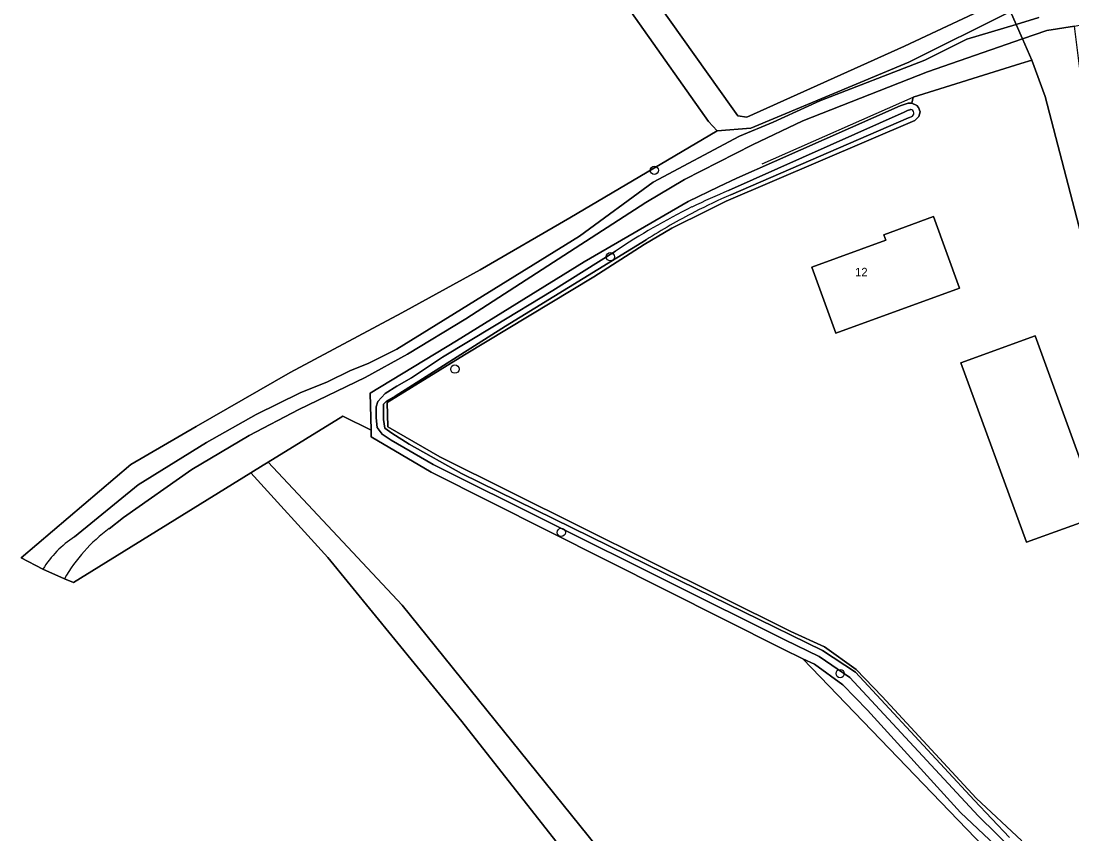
# Model space of a CAD drawing. Extents: x 163859 to 164644, y 379566 to 382155.
# Drawn here: x 164255.7 to 164380.2, y 381497.9 to 381594.2 of the extents above; entities that cross this region are included whole.
import ezdxf

# ---------------------------------------------------------------- set-up
doc = ezdxf.new("R2010")
doc.units = 0
for name, color, linetype in [('IMGEO_Boom', 7, 'Continuous'), ('IMGEO_Bouwland', 7, 'Continuous'), ('IMGEO_Erf', 7, 'Continuous'), ('IMGEO_Grasland_overig', 7, 'Continuous'), ('IMGEO_Groenvoorziening', 7, 'Continuous'), ('IMGEO_Hek', 7, 'Continuous'), ('IMGEO_Oever', 7, 'Continuous'), ('IMGEO_Pand', 7, 'Continuous'), ('IMGEO_Pand_nummerreeks', 7, 'Continuous'), ('IMGEO_Rijbaan_lokaal_onverhard', 7, 'Continuous'), ('IMGEO_Waterloop', 7, 'Continuous')]:
    doc.layers.add(name, color=color, linetype=linetype)

msp = doc.modelspace()

# ---------------------------------------------------------------- linework, layer by layer
at = {"layer": 'IMGEO_Boom'}
for centre in [(164330.75, 381576.5), (164325.53, 381566.25), (164307.12, 381552.94), (164319.72, 381533.59), (164352.76, 381516.86)]:
    msp.add_circle(centre, 0.489, dxfattribs=at)
at = {"layer": 'IMGEO_Bouwland'}
msp.add_lwpolyline([(164355.54, 381450.6), (164307.96, 381511.18), (164292.08, 381530.61), (164282.94, 381540.64), (164261.94, 381527.66), (164260.87, 381528.09), (164258.3, 381529.24), (164255.73, 381530.58), (164268.74, 381541.65), (164276.47, 381546.15), (164287.59, 381552.54), (164300.85, 381559.61), (164310.1, 381564.69), (164320.74, 381570.88), (164338.17, 381581.17), (164337.15, 381582.3), (164311.21, 381619.04)], dxfattribs=at)
msp.add_lwpolyline([(164285.02, 381541.92), (164300.88, 381524.96), (164324.9, 381495.18), (164345.91, 381468.69), (164361.95, 381448.81), (164380.14, 381426.39), (164393.19, 381411.03), (164409.6, 381438.92), (164409.07, 381444.14), (164407.24, 381453.04), (164404.26, 381474.32), (164397.81, 381497.74), (164374.92, 381491), (164348.35, 381518.62), (164345.94, 381519.8), (164304.33, 381540.74), (164297.21, 381544.93), (164297.2, 381545.69), (164293.83, 381547.35)], close=True, dxfattribs=at)
at = {"layer": 'IMGEO_Erf'}
for points in [[(164360.65, 381617.95), (164344.82, 381642.8), (164342.85, 381642.58), (164338.8, 381641.77), (164327.26, 381636.72), (164319.71, 381632.45), (164314.46, 381629.79), (164310.8, 381628.87), (164308.85, 381629.06), (164308.78, 381627.38), (164311.6, 381623.07), (164325.22, 381604.63), (164340.03, 381583.8), (164340.63, 381582.95), (164341.72, 381582.81), (164360.39, 381591.19), (164372.33, 381596.86), (164373.03, 381597.19), (164374.16, 381597.69), (164365.76, 381610.9)], [(164352.26, 381557.21), (164349.42, 381565.03), (164358.15, 381568.22), (164357.92, 381568.87), (164363.81, 381571.02), (164366.9, 381562.54)], [(164367.06, 381553.7), (164375.84, 381556.9), (164383.59, 381535.61), (164374.81, 381532.42)]]:
    msp.add_lwpolyline(points, close=True, dxfattribs=at)
msp.add_lwpolyline([(164394.23, 381519.23), (164377.05, 381585.25), (164375.48, 381589.55), (164374.16, 381589.15), (164361.39, 381585.17), (164361.25, 381584.45), (164361.82, 381584.19), (164362.04, 381583.93), (164362.24, 381583.41), (164362.09, 381582.86), (164361.61, 381582.39), (164339.27, 381572.83), (164337.03, 381571.73), (164332.8, 381569.66), (164329.55, 381567.7), (164323.57, 381563.86), (164308.27, 381554.65), (164299.1, 381548.97), (164299.19, 381546.09), (164305.32, 381542.54), (164346.92, 381521.84), (164350.89, 381520.01), (164354.66, 381517.34), (164357.74, 381514.15), (164368.85, 381502.09), (164374.28, 381497.03)], dxfattribs=at)
at = {"layer": 'IMGEO_Grasland_overig'}
for points in [[(164321.9, 381568.69), (164330.62, 381575.1), (164340.85, 381580.53), (164344.81, 381582.22), (164350.33, 381584.74), (164362.79, 381589.53), (164367.77, 381592.02), (164373.62, 381593.79), (164372.93, 381595.33), (164360.91, 381589.33), (164342.17, 381581.51), (164338.17, 381581.17), (164320.74, 381570.88), (164310.1, 381564.69), (164300.85, 381559.61), (164287.59, 381552.54), (164276.47, 381546.15), (164268.74, 381541.65), (164255.73, 381530.58), (164258.3, 381529.24)], [(164329.74, 381572.7), (164334.32, 381575.4), (164342.38, 381579.5), (164348.34, 381582.35), (164363.11, 381588.17), (164374.37, 381592.06), (164373.62, 381593.79), (164367.77, 381592.02), (164362.79, 381589.53), (164350.33, 381584.74), (164344.81, 381582.22), (164340.85, 381580.53), (164330.62, 381575.1), (164321.9, 381568.69), (164300.23, 381555.29), (164296.85, 381553.59), (164294.75, 381552.79), (164292.05, 381551.44), (164288.81, 381550.12), (164283.59, 381547.57), (164277.71, 381544.24), (164269.61, 381539.21), (164262.05, 381533.06)], [(164260.87, 381528.09), (164261.94, 381527.66), (164282.94, 381540.64), (164284.42, 381541.54), (164285.02, 381541.92), (164293.83, 381547.35), (164297.2, 381545.69), (164297.1, 381550.07), (164307.31, 381556.3), (164322.44, 381565.66), (164334.75, 381572.82), (164338.35, 381574.54), (164340.51, 381575.55), (164344.96, 381577.54), (164359.85, 381584.14), (164360.81, 381584.45), (164361.25, 381584.45), (164361.39, 381585.17), (164374.16, 381589.15), (164375.48, 381589.55), (164374.37, 381592.06), (164363.11, 381588.17), (164348.34, 381582.35), (164342.38, 381579.5), (164334.32, 381575.4), (164329.74, 381572.7), (164308.43, 381558.91), (164301.49, 381554.72), (164296.49, 381551.95), (164288.63, 381548.14), (164282.77, 381545.07), (164275.97, 381541.06), (164267.86, 381535.37), (164266.17, 381534.03)], [(164266.17, 381534.03), (164267.86, 381535.37), (164275.97, 381541.06), (164282.77, 381545.07), (164288.63, 381548.14), (164296.49, 381551.95), (164301.49, 381554.72), (164308.43, 381558.91), (164329.74, 381572.7)], [(164262.05, 381533.06), (164269.61, 381539.21), (164277.71, 381544.24), (164283.59, 381547.57), (164288.81, 381550.12), (164292.05, 381551.44), (164294.75, 381552.79), (164296.85, 381553.59), (164300.23, 381555.29), (164321.9, 381568.69)], [(164324.9, 381495.18), (164300.88, 381524.96), (164285.02, 381541.92), (164284.42, 381541.54), (164282.94, 381540.64), (164292.08, 381530.61), (164307.96, 381511.18), (164355.54, 381450.6)], [(164258.3, 381529.24), (164260.87, 381528.09)]]:
    msp.add_lwpolyline(points, dxfattribs=at)
for points in [[(164392.11, 381552.47), (164390.65, 381553.68), (164390.08, 381554.71), (164388.77, 381561.19), (164381.76, 381583.47), (164380.51, 381593.56), (164377.23, 381593.05), (164374.37, 381592.06), (164375.48, 381589.55), (164377.05, 381585.25), (164394.23, 381519.23), (164389.32, 381551.69)], [(164403.38, 381480.67), (164403.25, 381483.47), (164403.76, 381484.04), (164404.03, 381484.15), (164403.46, 381487.71), (164402.44, 381487.77), (164402.22, 381489.44), (164399.72, 381498.97), (164381.15, 381493.56), (164378.9, 381492.55), (164376.45, 381492.51), (164374.19, 381493.46), (164372.5, 381495.24), (164367, 381500.41), (164355.98, 381512.51), (164353.09, 381515.54), (164349.7, 381517.97), (164348.35, 381518.62), (164374.92, 381491), (164397.81, 381497.74), (164404.26, 381474.32)]]:
    msp.add_lwpolyline(points, close=True, dxfattribs=at)
for centre, radius, start, end in [((164277.4, 381518.7), 19.01, 126.2236, 150.3885), ((164277.4, 381518.7), 19.01, 126.2236, 150.3885), ((164269.14, 381522.37), 12.83, 123.5518, 147.6149), ((164269.14, 381522.37), 12.83, 123.5518, 147.6149)]:
    msp.add_arc(centre, radius, start, end, dxfattribs=at)
at = {"layer": 'IMGEO_Groenvoorziening'}
msp.add_lwpolyline([(164357.73, 381627.06), (164346.74, 381643.35), (164343.74, 381644.16), (164341.85, 381643.92), (164342.85, 381642.58), (164344.82, 381642.8), (164360.65, 381617.95), (164365.76, 381610.9), (164374.16, 381597.69), (164373.03, 381597.19), (164373.82, 381595.78), (164372.93, 381595.33), (164373.62, 381593.79), (164376.28, 381594.59)], dxfattribs=at)
at = {"layer": 'IMGEO_Hek'}
for points in [[(164374.16, 381589.15), (164375.48, 381589.55)], [(164343.52, 381577.27), (164361.39, 381585.17)]]:
    msp.add_lwpolyline(points, dxfattribs=at)
at = {"layer": 'IMGEO_Oever'}
for points in [[(164374.28, 381497.03), (164368.85, 381502.09), (164357.74, 381514.15), (164354.66, 381517.34), (164350.89, 381520.01), (164346.92, 381521.84), (164305.32, 381542.54), (164299.19, 381546.09), (164299.1, 381548.97), (164308.27, 381554.65), (164323.57, 381563.86), (164329.55, 381567.7), (164332.8, 381569.66), (164337.03, 381571.73), (164339.27, 381572.83), (164361.61, 381582.39), (164362.09, 381582.86), (164362.24, 381583.41), (164362.04, 381583.93), (164361.82, 381584.19), (164361.25, 381584.45), (164360.81, 381584.45), (164359.85, 381584.14), (164344.96, 381577.54), (164340.51, 381575.55), (164338.35, 381574.54), (164334.75, 381572.82), (164322.44, 381565.66), (164307.31, 381556.3), (164297.1, 381550.07), (164297.2, 381545.69), (164297.21, 381544.93), (164304.33, 381540.74), (164345.94, 381519.8), (164348.35, 381518.62), (164349.7, 381517.97), (164353.09, 381515.54), (164355.98, 381512.51), (164367, 381500.41), (164372.5, 381495.24)], [(164339.54, 381574.12), (164360.32, 381583.37), (164360.72, 381583.6), (164361.11, 381583.72)], [(164361.17, 381582.83), (164360.96, 381582.74), (164360.87, 381582.71), (164339.8, 381573.6)], [(164329.77, 381568.26), (164313.12, 381558.01), (164300.03, 381549.74), (164299, 381549.16), (164298.67, 381548.78), (164298.67, 381546.95), (164298.84, 381545.93), (164299.65, 381545.33), (164301.71, 381544.03), (164307.92, 381540.57), (164331.96, 381528.77), (164350.67, 381519.59), (164354.57, 381517.03), (164368.63, 381501.86), (164372.82, 381497.44)], [(164311.83, 381558.05), (164318.74, 381562.27), (164326.13, 381566.92)], [(164373.54, 381495.65), (164369.1, 381500), (164353.9, 381516.4), (164350.27, 381518.88), (164346.22, 381520.84), (164304.55, 381541.63), (164299.58, 381544.5), (164298.49, 381545.22), (164297.92, 381546.04), (164297.78, 381547.18), (164297.8, 381548.46), (164298, 381549.11), (164298.88, 381550.05), (164300.24, 381550.9), (164301.98, 381551.89), (164305.64, 381554.34), (164311.83, 381558.05)]]:
    msp.add_lwpolyline(points, dxfattribs=at)
for centre, radius, start, end in [((164361.02, 381583.27), 0.461, 289.4939, 79.0169), ((164369.92, 381501.27), 78.92, 112.6358, 116.099), ((164370.05, 381504.51), 75.42, 113.6483, 117.2335), ((164369.5, 381502.22), 77.89, 116.129, 123.8321), ((164369.14, 381506.27), 73.44, 117.2293, 122.4145)]:
    msp.add_arc(centre, radius, start, end, dxfattribs=at)
at = {"layer": 'IMGEO_Pand'}
for points in [[(164352.26, 381557.21), (164366.9, 381562.54), (164363.81, 381571.02), (164357.92, 381568.87), (164358.15, 381568.22), (164349.42, 381565.03)], [(164374.81, 381532.42), (164383.59, 381535.61), (164375.84, 381556.9), (164367.06, 381553.7)]]:
    msp.add_lwpolyline(points, close=True, dxfattribs=at)
at = {"layer": 'IMGEO_Rijbaan_lokaal_onverhard'}
msp.add_lwpolyline([(164376.28, 381594.59), (164373.62, 381593.79), (164374.37, 381592.06), (164377.23, 381593.05), (164380.51, 381593.56), (164384.86, 381594.48), (164414.14, 381600.68)], dxfattribs=at)
at = {"layer": 'IMGEO_Waterloop'}
for points in [[(164311.21, 381619.04), (164337.15, 381582.3), (164338.17, 381581.17), (164342.17, 381581.51), (164360.91, 381589.33), (164372.93, 381595.33)], [(164372.33, 381596.86), (164360.39, 381591.19), (164341.72, 381582.81), (164340.63, 381582.95), (164340.03, 381583.8), (164325.22, 381604.63)], [(164361.11, 381583.72), (164360.72, 381583.6), (164360.32, 381583.37), (164339.54, 381574.12)], [(164339.8, 381573.6), (164360.87, 381582.71), (164360.96, 381582.74), (164361.17, 381582.83)], [(164372.82, 381497.44), (164368.63, 381501.86), (164354.57, 381517.03), (164350.67, 381519.59), (164331.96, 381528.77), (164307.92, 381540.57), (164301.71, 381544.03), (164299.65, 381545.33), (164298.84, 381545.93), (164298.67, 381546.95), (164298.67, 381548.78), (164299, 381549.16), (164300.03, 381549.74), (164313.12, 381558.01), (164329.77, 381568.26)], [(164326.13, 381566.92), (164318.74, 381562.27), (164311.83, 381558.05), (164305.64, 381554.34), (164301.98, 381551.89), (164300.24, 381550.9), (164298.88, 381550.05), (164298, 381549.11), (164297.8, 381548.46), (164297.78, 381547.18), (164297.92, 381546.04), (164298.49, 381545.22), (164299.58, 381544.5), (164304.55, 381541.63), (164346.22, 381520.84), (164350.27, 381518.88), (164353.9, 381516.4), (164369.1, 381500), (164373.54, 381495.65)]]:
    msp.add_lwpolyline(points, dxfattribs=at)
for centre, radius, start, end in [((164361.02, 381583.27), 0.461, 289.4939, 79.0169), ((164369.92, 381501.27), 78.92, 112.6358, 116.099), ((164370.05, 381504.51), 75.42, 113.6483, 117.2335), ((164369.5, 381502.22), 77.89, 116.129, 123.8321), ((164369.14, 381506.27), 73.44, 117.2293, 122.4145)]:
    msp.add_arc(centre, radius, start, end, dxfattribs=at)

# ---------------------------------------------------------------- texts
at = {"layer": 'IMGEO_Pand_nummerreeks'}
msp.add_text('12', height=1, dxfattribs=at).set_placement((164354.52, 381563.94))

doc.saveas('drawing.dxf')
